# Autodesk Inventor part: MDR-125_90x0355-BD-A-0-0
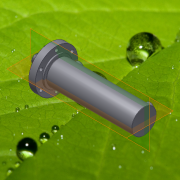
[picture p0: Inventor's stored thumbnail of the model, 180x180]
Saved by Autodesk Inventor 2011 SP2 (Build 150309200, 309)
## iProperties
Created: 2015-10
Part Number: MDR-125_90x0355-BD-A-0-0
Material: Сталь
Document SubType Name: Modeling
Designer: Дорохин
Mass: 84885 g
Surface Area: 4057.42 cm^2
Volume: 10813.4 cm^3
Density: 7.85 g/cm^3
Author: Дорохин
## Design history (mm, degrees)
sketch "Эскиз1"
  geometry: L1 (0, 0)-(0, 24); L2 (0, 24)-(2, 26); L3 (2, 26)-(45, 26); L4 (45, 26)-(47, 24); L5 (47, 24)-(55, 24); L6 (55, 24)-(55, 41.5); L7 (55, 41.5)-(56, 42.5); L8 (56, 42.5)-(70, 42.5); L9 (70, 42.5)-(72.5, 45); L10 (72.5, 45)-(80, 45); L11 (80, 45)-(80, 84); L12 (80, 84)-(83, 84); L13 (83, 84)-(83, 124); L14 (83, 124)-(84, 125); L15 (84, 125)-(122, 125); L16 (122, 125)-(123, 124); L17 (123, 124)-(123, 85); L18 (123, 85)-(131, 85); L19 (131, 85)-(133, 83); L20 (133, 83)-(133, 70); L21 (133, 70)-(138, 70); L22 (138, 70)-(138, 72.5); L23 (138, 72.5)-(636, 72.5); L24 (638, 70.5)-(638, 0); L25 (638, 0)-(0, 0); L26 (638, 70.5)-(636, 72.5); 1 further point
  constraints: 52 end point, 14 perpendicular, 4 parallel, 2 point on line, 2 vertical
  dimensions: "d0" = 55 distance between parallel lines of L6 L1; "d1" = 80 distance between parallel lines of L1 L11; "d3" = 40 distance between parallel lines of L17 L13; "d4" = 53 distance between parallel lines of L20 L11; "d6" = 558 distance between parallel lines of L24 L11; "d7" = 3 distance between parallel lines of L13 L11; "d8" = 45 deg angle of L15 L14; "d9" = 45 deg angle of L15 L16; "d10" = 145 diameter of L23 L25; "d11" = 170 diameter of L18 L25; "d12" = 250 diameter of L15 L25; "d13" = 248 diameter of L13.end L25 (computed from d12); "d14" = 248 diameter of L16.end L25 (computed from d12); "d15" = 45 deg angle of L18 L19; "d16" = 140 diameter of L21 L25; "d17" = 5 distance between parallel lines of L22 L20; "d18" = 166 diameter of L19.end L25 (computed from d11); "d19" = 168 diameter of L12 L25; "d20" = 90 diameter of L10 L25; "d21" = 45 deg angle of L10 L9; "d22" = 85 diameter of L8 L25; "d23" = 83 diameter of L6.end L25; "d26" = 15 distance from line of L8.end L6; "d27" = 52 diameter of L3 L25; "d28" = 45 deg angle of L3 L2; "d29" = 48 diameter of L1.end L25; "d30" = 48 diameter of L5 L25; "d31" = 45 deg angle of L3 L4 (derived); "d32" = 10 distance from line of L6 L3.end; "d34" = 2 distance of L24.start point (638, 72.5); "d35" = 2 distance of L23.end point (638, 72.5) (= d34)
revolve "Вращение1" sketch "Эскиз1" stored, may be unused: angle "d33" = 90 deg
sketch "Эскиз2"
  geometry: L1 (-83, 124)-(-83, -124) reference; L2 (-638, 70.5)-(-638, -70.5) reference; C1 r 25 at (-168, 0); C2 r 25 at (-581, 0); 1 further point
  constraints: 2 centre point
  dimensions: "d36" = 50 diameter of C1; "d37" = 50 diameter of C2; "d38" = 0 vertical distance of C2.centre C1.centre; "d39" = 0 vertical distance of C1.centre point (0, 0); "d42" = 85 distance from line of C1.centre L1; "d43" = 57 distance from line of L2 C2.centre
extrude "Выдавливание1" join sketch "Эскиз2" distance "d44" = 91; taper "d45" = 0 deg
hole "Отверстие1" diameter "d48" = 24.117; stored, may be unused: countersink angle "d52" = 90 deg, drill point angle "d54" = 118 deg; dims "d46" = 10, "d47" = 10, "d49" = 25, "d50" = 28, "d51" = 2, "d53" = 30
hole "Отверстие2" diameter "d57" = 24.117; stored, may be unused: countersink angle "d61" = 90 deg, drill point angle "d63" = 118 deg; dims "d55" = 10, "d56" = 10, "d58" = 25, "d59" = 28, "d60" = 2, "d62" = 30
chamfer "Фаска1" distance "d64" = 1; stored, may be unused: second distance "d65" = 2, angle "d66" = 45 deg
sketch "Эскиз3" dims "d68" = 210
  geometry: C1 r 124 at (0, 0) reference; C2 r 84 at (0, 0) reference; 2 further points
  constraints: 1 coincident, 1 horizontal alignment, 2 other
  dimensions: "d67" = 0 vertical distance of point (105, 0) C1.centre
hole "Отверстие3" sketch "Эскиз3" at (105, 0) diameter "d69" = 21; stored, may be unused: countersink angle "d73" = 90 deg, drill point angle "d75" = 118 deg; dims "d70" = 25, "d71" = 30, "d72" = 2, "d74" = 30
pattern_circular "Круговой массив1" dims angle "d77" = 360 deg
feature "Резьба1" dims "d79" = 10, "d80" = 0
feature "Резьба2" dims "d81" = 10, "d82" = 0
sketch "Эскиз4"
  geometry: L1 (55, -41.5)-(55, 41.5) reference; C1 r 2.5 at (62.5, 0); 1 further point
  constraints: 1 centre point
  dimensions: "d83" = 5 diameter of C1; "d84" = 0 vertical distance of C1.centre point (0, 0); "d85" = 7.5 distance from line of L1 C1.centre
extrude "Выдавливание2" cut sketch "Эскиз4" stored distance "d86" = 90; taper "d87" = 0 deg
node "Твердое тело1"
